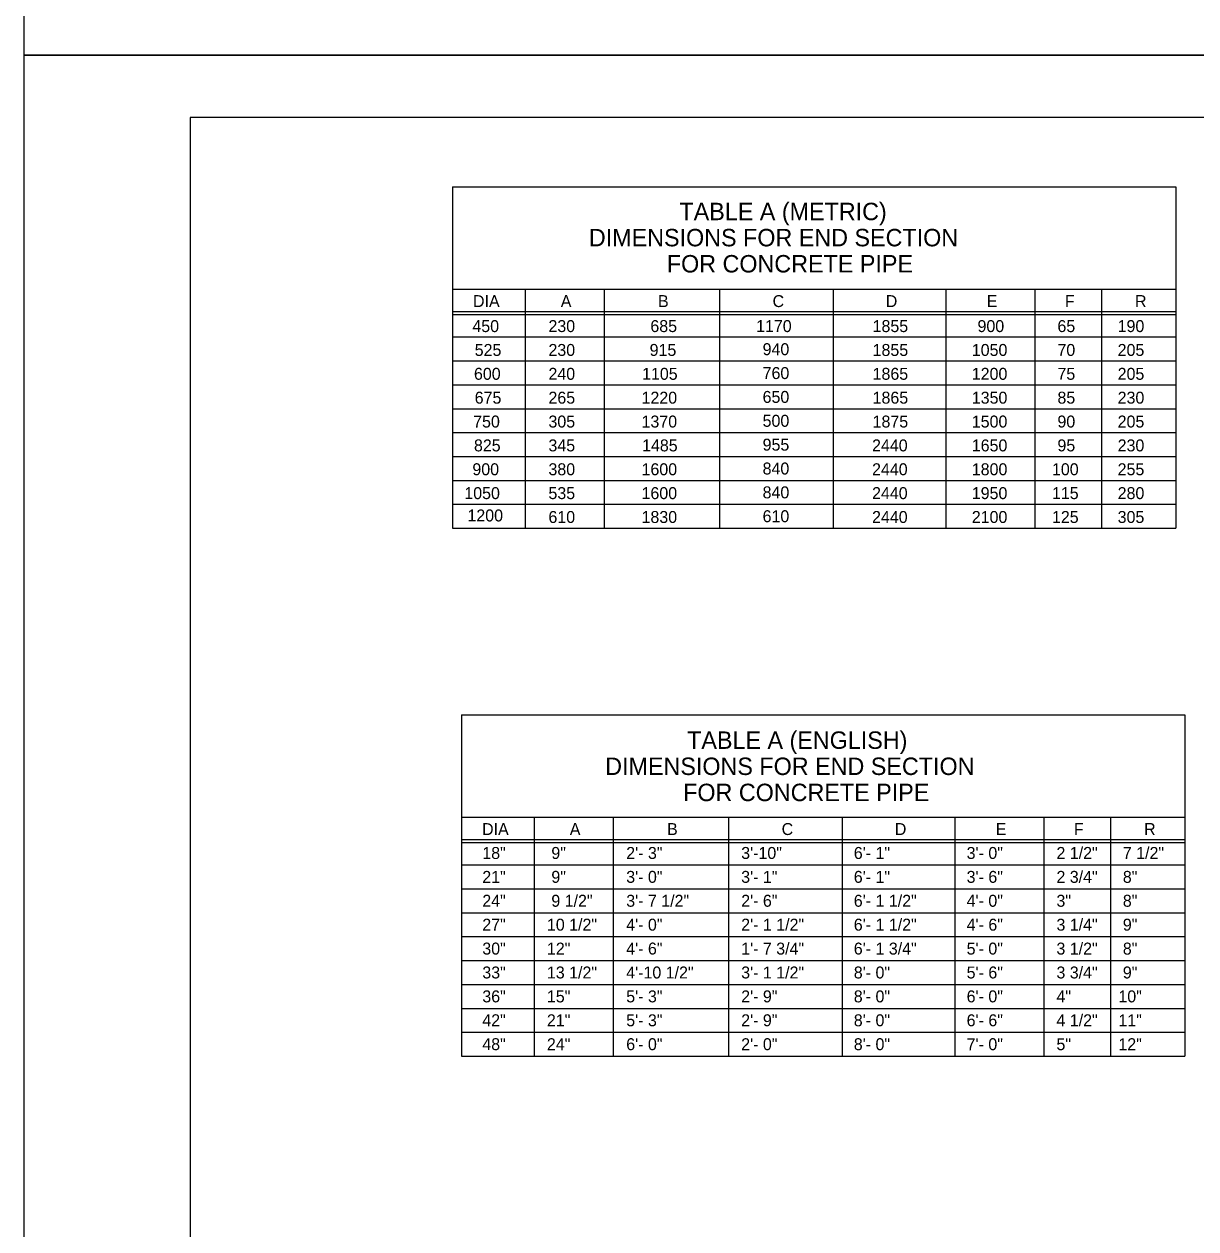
# Model space of a CAD drawing. Extents: x -17 to 888, y -473 to 715.
# Drawn here: x -17.2 to 265, y -161.9 to 128.4 of the extents above; entities that cross this region are included whole.
import ezdxf

# ---------------------------------------------------------------- set-up
doc = ezdxf.new("R2010")
doc.units = 0
for name, color, linetype in [('1', 7, 'Continuous'), ('3', 7, 'Continuous'), ('PLT-BNDY', 7, 'Continuous')]:
    doc.layers.add(name, color=color, linetype=linetype)

msp = doc.modelspace()

# ---------------------------------------------------------------- linework, layer by layer
at = {"layer": '1'}
msp.add_lwpolyline([(808.79, -458.11), (808.79, 105.89), (22.79, 105.89), (22.79, -458.11), (808.79, -458.11), (808.79, -431.75), (608.79, -431.75), (608.79, -367.07), (808.79, -367.07), (808.79, -338.11), (608.79, -338.11), (608.79, -458.11), (687.6, -458.11), (687.6, -431.75), (687.6, -458.11), (764.6, -458.11), (764.6, -431.75), (764.6, -444.07), (808.79, -444.07)], dxfattribs=at)
at = {"layer": '3'}
for p, q in [((85.97, 89.16), (260.17, 89.16)), ((85.97, 89.16), (85.97, 6.93)), ((260.17, 89.16), (260.17, 6.93)), ((85.97, 64.52), (260.17, 64.52)), ((103.49, 64.52), (103.49, 6.93)), ((103.49, 64.52), (122.46, 64.52)), ((122.46, 64.52), (122.46, 6.93)), ((122.46, 64.52), (150.25, 64.52)), ((150.25, 64.52), (150.25, 6.93)), ((150.25, 64.52), (177.64, 64.52)), ((177.64, 64.52), (177.64, 6.93)), ((177.64, 64.52), (204.77, 64.52)), ((204.77, 64.52), (204.77, 6.93)), ((204.77, 64.52), (226.24, 64.52)), ((226.24, 64.52), (226.24, 6.93)), ((226.24, 64.52), (242.31, 64.52)), ((242.31, 64.52), (242.31, 6.93)), ((242.31, 64.52), (260.17, 64.52)), ((85.97, 59.45), (85.97, 58.76)), ((85.97, 59.11), (260.17, 59.11)), ((85.97, 58.42), (260.17, 58.42)), ((85.97, 53), (260.17, 53)), ((85.97, 47.24), (260.17, 47.24)), ((85.97, 41.48), (260.17, 41.48)), ((85.97, 35.72), (260.17, 35.72)), ((85.97, 29.97), (260.17, 29.97)), ((85.97, 24.21), (260.17, 24.21)), ((85.97, 18.45), (260.17, 18.45)), ((85.97, 12.69), (260.17, 12.69)), ((85.97, 6.93), (260.17, 6.93)), ((85.97, 6.93), (85.97, 6.93)), ((260.17, 6.93), (260.17, 6.93)), ((88.15, -38.07), (262.34, -38.07)), ((88.15, -38.07), (88.15, -120.3)), ((262.34, -38.07), (262.34, -120.3)), ((88.15, -62.7), (262.34, -62.7)), ((105.67, -62.7), (105.67, -120.3)), ((105.67, -62.7), (124.64, -62.7)), ((124.64, -62.7), (124.64, -120.3)), ((124.64, -62.7), (152.42, -62.7)), ((152.42, -62.7), (152.42, -120.3)), ((152.42, -62.7), (179.82, -62.7)), ((179.82, -62.7), (179.82, -120.3)), ((179.82, -62.7), (206.95, -62.7)), ((206.95, -62.7), (206.95, -120.3)), ((206.95, -62.7), (228.41, -62.7)), ((228.41, -62.7), (228.41, -120.3)), ((228.41, -62.7), (244.48, -62.7)), ((244.48, -62.7), (244.48, -120.3)), ((244.48, -62.7), (262.34, -62.7)), ((88.15, -67.77), (88.15, -68.46)), ((88.15, -68.12), (262.34, -68.12)), ((88.15, -68.8), (262.34, -68.8)), ((88.15, -74.22), (262.34, -74.22)), ((88.15, -79.98), (262.34, -79.98)), ((88.15, -85.74), (262.34, -85.74)), ((88.15, -91.5), (262.34, -91.5)), ((88.15, -97.26), (262.34, -97.26)), ((88.15, -103.02), (262.34, -103.02)), ((88.15, -108.78), (262.34, -108.78)), ((88.15, -114.54), (262.34, -114.54)), ((88.15, -120.3), (262.34, -120.3)), ((88.15, -120.3), (88.15, -120.3)), ((262.34, -120.3), (262.34, -120.3))]:
    msp.add_line(p, q, dxfattribs=at)
at = {"layer": 'PLT-BNDY'}
for points in [[(-17.21, 714.89), (823.79, 714.89), (823.79, 120.89), (-17.21, 120.89)], [(-17.21, 120.89), (823.79, 120.89), (823.79, -473.11), (-17.21, -473.11)]]:
    msp.add_lwpolyline(points, close=True, dxfattribs=at)

# ---------------------------------------------------------------- texts
at = {"layer": '3'}
for s, height, p in [('TABLE A (METRIC)', 4.2, (140.63, 81.14)), ('DIMENSIONS FOR END SECTION', 4.2, (118.82, 74.84)), ('FOR CONCRETE PIPE', 4.2, (137.59, 68.54)), ('DIA', 2.88, (90.91, 60.2)), ('A', 2.88, (112.05, 60.2)), ('A', 2.88, (112.05, 60.2)), ('B', 2.88, (135.47, 60.2)), ('C', 2.88, (163.06, 60.2)), ('D', 2.88, (190.32, 60.2)), ('E', 2.88, (214.63, 60.2)), ('F', 2.88, (233.46, 60.2)), ('R', 2.88, (250.35, 60.2)), ('450 ', 2.88, (90.76, 54.18)), ('230 ', 2.88, (109.08, 54.18)), ('685 ', 2.88, (133.63, 54.18)), ('1170', 2.88, (159.09, 54.18)), ('1855', 2.88, (187.15, 54.18)), ('900 ', 2.88, (212.42, 54.18)), ('65  ', 2.88, (231.67, 54.18)), ('190 ', 2.88, (246.17, 54.18)), ('525 ', 2.88, (91.32, 48.43)), ('230 ', 2.88, (109.08, 48.43)), ('915 ', 2.88, (133.45, 48.43)), ('940 ', 2.88, (160.66, 48.61)), ('1855', 2.88, (187.15, 48.43)), ('1050', 2.88, (211.04, 48.43)), ('70  ', 2.88, (231.67, 48.43)), ('205 ', 2.88, (246.17, 48.43)), ('600 ', 2.88, (91.14, 42.68)), ('240 ', 2.88, (109.08, 42.68)), ('1105', 2.88, (131.63, 42.68)), ('760 ', 2.88, (160.66, 42.86)), ('1865', 2.88, (187.15, 42.68)), ('1200', 2.88, (211.04, 42.68)), ('75  ', 2.88, (231.67, 42.68)), ('205 ', 2.88, (246.17, 42.68)), ('675 ', 2.88, (91.32, 36.93)), ('265 ', 2.88, (109.08, 36.93)), ('1220', 2.88, (131.5, 36.93)), ('650 ', 2.88, (160.66, 37.11)), ('1865', 2.88, (187.15, 36.93)), ('1350', 2.88, (211.04, 36.93)), ('85  ', 2.88, (231.67, 36.93)), ('230 ', 2.88, (246.17, 36.93)), ('750 ', 2.88, (90.95, 31.18)), ('305 ', 2.88, (109.08, 31.18)), ('1370', 2.88, (131.5, 31.18)), ('500 ', 2.88, (160.66, 31.36)), ('1875', 2.88, (187.15, 31.18)), ('1500', 2.88, (211.04, 31.18)), ('90  ', 2.88, (231.67, 31.18)), ('205 ', 2.88, (246.17, 31.18)), ('825 ', 2.88, (91.14, 25.43)), ('345 ', 2.88, (109.08, 25.43)), ('1485', 2.88, (131.63, 25.43)), ('955 ', 2.88, (160.66, 25.61)), ('2440', 2.88, (187.02, 25.43)), ('1650', 2.88, (211.04, 25.43)), ('95  ', 2.88, (231.67, 25.43)), ('230 ', 2.88, (246.17, 25.43)), ('900 ', 2.88, (90.76, 19.68)), ('380 ', 2.88, (109.08, 19.68)), ('1600', 2.88, (131.5, 19.68)), ('840 ', 2.88, (160.66, 19.86)), ('2440', 2.88, (187.02, 19.68)), ('1800', 2.88, (211.04, 19.68)), ('100 ', 2.88, (230.35, 19.68)), ('255 ', 2.88, (246.17, 19.68)), ('1050', 2.88, (88.82, 13.93)), ('535 ', 2.88, (109.08, 13.93)), ('1600', 2.88, (131.5, 13.93)), ('840 ', 2.88, (160.66, 14.11)), ('2440', 2.88, (187.02, 13.93)), ('1950', 2.88, (211.04, 13.93)), ('115 ', 2.88, (230.35, 13.93)), ('280 ', 2.88, (246.17, 13.93)), ('1200', 2.88, (89.57, 8.55)), ('610 ', 2.88, (109.08, 8.18)), ('1830', 2.88, (131.5, 8.18)), ('610 ', 2.88, (160.66, 8.36)), ('2440', 2.88, (187.02, 8.18)), ('2100', 2.88, (211.04, 8.18)), ('125 ', 2.88, (230.35, 8.18)), ('305 ', 2.88, (246.17, 8.18)), ('TABLE A (ENGLISH)', 4.2, (142.48, -46.25)), ('DIMENSIONS FOR END SECTION', 4.2, (122.75, -52.55)), ('FOR CONCRETE PIPE', 4.2, (141.52, -58.85)), ('DIA', 2.88, (93.09, -67.03)), ('A', 2.88, (114.22, -67.02)), ('A', 2.88, (114.22, -67.02)), ('B', 2.88, (137.65, -67.02)), ('C', 2.88, (165.24, -67.02)), ('D', 2.88, (192.5, -67.02)), ('E', 2.88, (216.81, -67.02)), ('F', 2.88, (235.63, -67.02)), ('R', 2.88, (252.53, -67.02)), ('18"', 2.88, (93.15, -72.79)), (' 9"', 2.88, (108.71, -72.78)), ('2\'- 3"', 2.88, (127.81, -72.78)), ('3\'-10"', 2.88, (155.5, -72.78)), ('6\'- 1"', 2.88, (182.62, -72.78)), ('3\'- 0"', 2.88, (209.8, -72.78)), ('2 1/2"', 2.88, (231.43, -72.78)), (' 7 1/2"', 2.88, (246.35, -72.78)), ('21"', 2.88, (93.15, -78.55)), (' 9"', 2.88, (108.71, -78.54)), ('3\'- 0"', 2.88, (127.81, -78.54)), ('3\'- 1"', 2.88, (155.5, -78.54)), ('6\'- 1"', 2.88, (182.62, -78.54)), ('3\'- 6"', 2.88, (209.8, -78.54)), ('2 3/4"', 2.88, (231.43, -78.54)), (' 8"', 2.88, (246.35, -78.54)), (' 9 1/2"', 2.88, (108.71, -84.3)), ('3\'- 7 1/2"', 2.88, (127.81, -84.3)), ('6\'- 1 1/2"', 2.88, (182.62, -84.3)), ('24"', 2.88, (93.15, -84.3)), ('2\'- 6"', 2.88, (155.5, -84.3)), ('4\'- 0"', 2.88, (209.8, -84.3)), ('3"', 2.88, (231.43, -84.3)), (' 8"', 2.88, (246.35, -84.3)), ('10 1/2"', 2.88, (108.71, -90.06)), ('2\'- 1 1/2"', 2.88, (155.5, -90.06)), ('6\'- 1 1/2"', 2.88, (182.62, -90.06)), ('3 1/4"', 2.88, (231.43, -90.06)), ('27"', 2.88, (93.15, -90.06)), ('4\'- 0"', 2.88, (127.81, -90.06)), ('4\'- 6"', 2.88, (209.8, -90.06)), (' 9"', 2.88, (246.35, -90.06)), ('30"', 2.88, (93.15, -95.82)), ('12"', 2.88, (108.71, -95.82)), ('4\'- 6"', 2.88, (127.81, -95.82)), ('1\'- 7 3/4"', 2.88, (155.5, -95.82)), ('6\'- 1 3/4"', 2.88, (182.62, -95.82)), ('5\'- 0"', 2.88, (209.8, -95.82)), ('3 1/2"', 2.88, (231.43, -95.82)), (' 8"', 2.88, (246.35, -95.82)), ('33"', 2.88, (93.15, -101.58)), ('13 1/2"', 2.88, (108.71, -101.58)), ('4\'-10 1/2"', 2.88, (127.81, -101.58)), ('3\'- 1 1/2"', 2.88, (155.5, -101.58)), ('8\'- 0"', 2.88, (182.62, -101.58)), ('5\'- 6"', 2.88, (209.8, -101.58)), ('3 3/4"', 2.88, (231.43, -101.58)), (' 9"', 2.88, (246.35, -101.58)), ('36"', 2.88, (93.15, -107.34)), ('15"', 2.88, (108.71, -107.34)), ('5\'- 3"', 2.88, (127.81, -107.34)), ('2\'- 9"', 2.88, (155.5, -107.34)), ('8\'- 0"', 2.88, (182.62, -107.34)), ('6\'- 0"', 2.88, (209.8, -107.34)), ('4"', 2.88, (231.43, -107.34)), ('10"', 2.88, (246.35, -107.34)), ('42"', 2.88, (93.15, -113.09)), ('21"', 2.88, (108.71, -113.1)), ('5\'- 3"', 2.88, (127.81, -113.1)), ('2\'- 9"', 2.88, (155.5, -113.1)), ('8\'- 0"', 2.88, (182.62, -113.1)), ('6\'- 6"', 2.88, (209.8, -113.1)), ('4 1/2"', 2.88, (231.43, -113.1)), ('11"', 2.88, (246.35, -113.1)), ('48"', 2.88, (93.15, -118.85)), ('24"', 2.88, (108.71, -118.86)), ('6\'- 0"', 2.88, (127.81, -118.86)), ('2\'- 0"', 2.88, (155.5, -118.86)), ('8\'- 0"', 2.88, (182.62, -118.86)), ('7\'- 0"', 2.88, (209.8, -118.86)), ('5"', 2.88, (231.43, -118.86)), ('12"', 2.88, (246.35, -118.86))]:
    msp.add_text(s, height=height, dxfattribs=at).set_placement(p)

doc.saveas('drawing.dxf')
